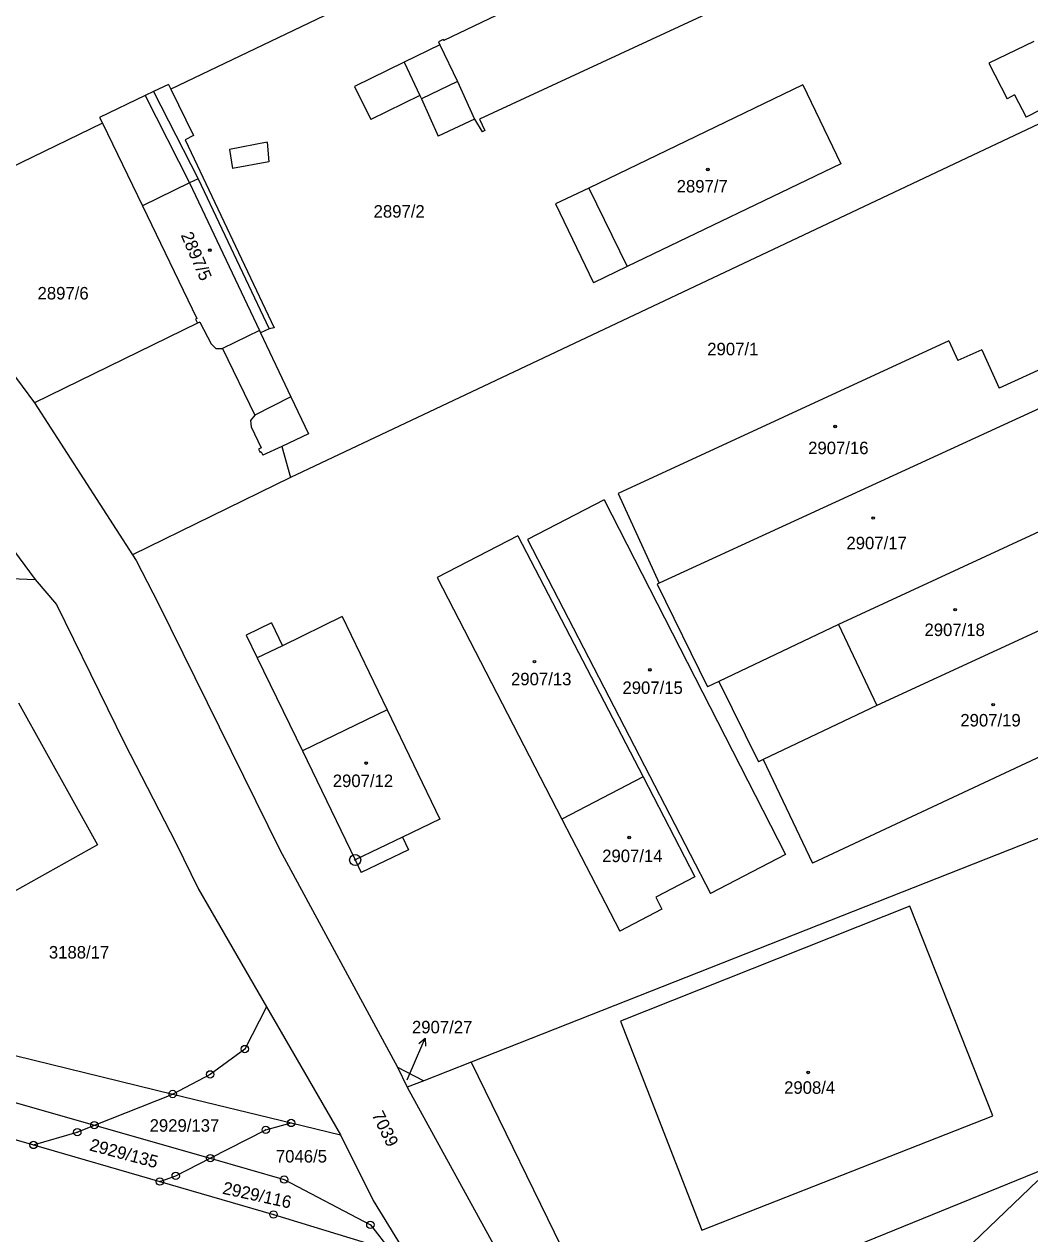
# Model space of a CAD drawing. Extents: x -593183 to -588034, y -1130415 to -1124994.
# Drawn here: x -591710.2 to -591573.4, y -1128134.3 to -1127969.7 of the extents above; entities that cross this region are included whole.
import ezdxf

# ---------------------------------------------------------------- set-up
doc = ezdxf.new("R2010")
doc.units = 0
for name, color, linetype in [('Vrstva 1', 7, 'Continuous'), ('Vrstva 16', 7, 'Continuous'), ('Vrstva 18', 7, 'Continuous'), ('Vrstva 19', 7, 'Continuous'), ('Vrstva 24', 7, 'Continuous'), ('Vrstva 25', 7, 'Continuous'), ('Vrstva 4', 7, 'Continuous')]:
    doc.layers.add(name, color=color, linetype=linetype)

msp = doc.modelspace()

# ---------------------------------------------------------------- linework, layer by layer
at = {"layer": 'Vrstva 1'}
for p, q in [((-591579.21, -1127925.41), (-591690.25, -1127978.58)), ((-591617.79, -1127955.04), (-591653.11, -1127971.96)), ((-591611.84, -1127965.78), (-591648.23, -1127982.66)), ((-591653.17, -1127971.83), (-591653.83, -1127972.14)), ((-591653.17, -1127971.83), (-591653.11, -1127971.96)), ((-591653.63, -1127972.55), (-591658.5, -1127974.93)), ((-591653.83, -1127972.14), (-591653.63, -1127972.55)), ((-591572.8, -1127972.09), (-591578.95, -1127975.03)), ((-591553.24, -1127974.41), (-591673.98, -1128031.42)), ((-591658.5, -1127974.93), (-591665.23, -1127978.21)), ((-591578.95, -1127975.03), (-591576.44, -1127979.88)), ((-591690.56, -1127977.93), (-591692.62, -1127978.92)), ((-591690.56, -1127977.93), (-591690.25, -1127978.58)), ((-591665.23, -1127978.21), (-591663.02, -1127982.72)), ((-591604.23, -1127977.99), (-591633.37, -1127992.03)), ((-591604.23, -1127977.99), (-591599.06, -1127988.76)), ((-591693.72, -1127979.45), (-591699.93, -1127982.45)), ((-591692.62, -1127978.92), (-591693.72, -1127979.45)), ((-591690.25, -1127978.58), (-591687.18, -1127984.91)), ((-591656.34, -1127979.46), (-591663.02, -1127982.72)), ((-591656.34, -1127979.46), (-591656.12, -1127979.91)), ((-591656.12, -1127979.91), (-591653.88, -1127985)), ((-591575.43, -1127979.36), (-591576.44, -1127979.88)), ((-591575.43, -1127979.36), (-591573.85, -1127982.4)), ((-591569.04, -1127979.92), (-591573.85, -1127982.4)), ((-591699.56, -1127983.22), (-591725.5, -1127995.8)), ((-591699.93, -1127982.45), (-591699.56, -1127983.22)), ((-591699.56, -1127983.22), (-591694.12, -1127994.46)), ((-591648.94, -1127982.66), (-591653.88, -1127985)), ((-591648.94, -1127982.66), (-591647.9, -1127984.39)), ((-591648.23, -1127982.66), (-591647.51, -1127984.21)), ((-591687.18, -1127984.91), (-591688.3, -1127985.46)), ((-591647.51, -1127984.21), (-591647.9, -1127984.39)), ((-591688.3, -1127985.46), (-591676.17, -1128011.05)), ((-591599.06, -1127988.76), (-591628.14, -1128002.7)), ((-591633.37, -1127992.03), (-591637.88, -1127994.2)), ((-591694.12, -1127994.46), (-591686.71, -1128009.79)), ((-591637.88, -1127994.2), (-591632.74, -1128004.91)), ((-591628.14, -1128002.7), (-591632.74, -1128004.91)), ((-591717.83, -1128009.1), (-591708.79, -1128021.27)), ((-591686.61, -1128010.41), (-591708.79, -1128021.27)), ((-591686.71, -1128009.79), (-591686.87, -1128009.87)), ((-591686.87, -1128009.87), (-591686.61, -1128010.41)), ((-591686.31, -1128010.27), (-591686.61, -1128010.41)), ((-591686.31, -1128010.27), (-591684.76, -1128013.22)), ((-591676.86, -1128011.19), (-591678.02, -1128011.74)), ((-591676.17, -1128011.05), (-591676.86, -1128011.19)), ((-591678.02, -1128011.74), (-591673.91, -1128020.42)), ((-591584.38, -1128012.82), (-591629.39, -1128033.58)), ((-591584.38, -1128012.82), (-591583.14, -1128015.51)), ((-591684.76, -1128013.22), (-591684.1, -1128013.85)), ((-591684.1, -1128013.85), (-591683.22, -1128013.86)), ((-591683.22, -1128013.86), (-591678.8, -1128022.93)), ((-591579.9, -1128014.03), (-591583.14, -1128015.51)), ((-591579.9, -1128014.03), (-591577.51, -1128019.24)), ((-591567.77, -1128014.77), (-591577.51, -1128019.24)), ((-591566.36, -1128019.38), (-591623.78, -1128045.8)), ((-591708.79, -1128021.27), (-591695.48, -1128041.92)), ((-591673.91, -1128020.42), (-591671.51, -1128025.47)), ((-591678.8, -1128022.93), (-591679.41, -1128023.63)), ((-591679.41, -1128023.63), (-591679.32, -1128024.5)), ((-591679.32, -1128024.5), (-591677.96, -1128027.37)), ((-591671.51, -1128025.47), (-591675.16, -1128027.19)), ((-591677.96, -1128027.37), (-591678.3, -1128027.54)), ((-591678.3, -1128027.54), (-591678.11, -1128028)), ((-591675.16, -1128027.19), (-591677.72, -1128028.39)), ((-591677.95, -1128027.92), (-591678.11, -1128028)), ((-591677.95, -1128027.92), (-591677.72, -1128028.39)), ((-591673.98, -1128031.42), (-591695.48, -1128041.92)), ((-591717.29, -1128033.73), (-591708.7, -1128045.26)), ((-591631.29, -1128034.44), (-591641.72, -1128039.83)), ((-591631.29, -1128034.44), (-591606.61, -1128082.7)), ((-591629.39, -1128033.58), (-591623.78, -1128045.8)), ((-591559.94, -1128033.16), (-591599.4, -1128051.4)), ((-591643.01, -1128039.33), (-591654.01, -1128044.99)), ((-591643.01, -1128039.33), (-591625.98, -1128072.13)), ((-591641.72, -1128039.83), (-591616.82, -1128088.01)), ((-591695.48, -1128041.92), (-591694.95, -1128042.68)), ((-591694.95, -1128042.68), (-591691.94, -1128048.6)), ((-591554.77, -1128044.23), (-591594.16, -1128062.43)), ((-591711.95, -1128045.16), (-591708.7, -1128045.26)), ((-591708.7, -1128045.26), (-591705.79, -1128048.66)), ((-591654.01, -1128044.99), (-591637.02, -1128077.86)), ((-591623.78, -1128045.8), (-591624.05, -1128045.93)), ((-591624.05, -1128045.93), (-591617.21, -1128059.87)), ((-591705.79, -1128048.66), (-591696.54, -1128067.54)), ((-591691.94, -1128048.6), (-591675.39, -1128082.06)), ((-591666.91, -1128050.32), (-591675.04, -1128054.28)), ((-591666.91, -1128050.32), (-591660.8, -1128063.02)), ((-591676.56, -1128051.16), (-591679.99, -1128052.83)), ((-591676.56, -1128051.16), (-591675.04, -1128054.28)), ((-591599.4, -1128051.4), (-591615.68, -1128059.14)), ((-591679.99, -1128052.83), (-591678.48, -1128055.95)), ((-591678.48, -1128055.95), (-591672.34, -1128068.57)), ((-591548.21, -1128058.27), (-591602.93, -1128083.84)), ((-591615.68, -1128059.14), (-591617.21, -1128059.87)), ((-591615.68, -1128059.14), (-591610.28, -1128070.1)), ((-591710.97, -1128062.06), (-591700.21, -1128081.39)), ((-591660.8, -1128063.02), (-591653.64, -1128077.88)), ((-591594.16, -1128062.43), (-591609.62, -1128069.78)), ((-591696.54, -1128067.54), (-591689.55, -1128081.1)), ((-591672.34, -1128068.57), (-591665.16, -1128083.43)), ((-591609.62, -1128069.78), (-591610.28, -1128070.1)), ((-591609.62, -1128069.78), (-591602.93, -1128083.84)), ((-591625.98, -1128072.13), (-591637.02, -1128077.86)), ((-591625.98, -1128072.13), (-591618.93, -1128085.71)), ((-591653.64, -1128077.88), (-591658.72, -1128080.33)), ((-591565.82, -1128078), (-591649.36, -1128110.92)), ((-591637.02, -1128077.86), (-591629.13, -1128093.09)), ((-591658.72, -1128080.33), (-591657.9, -1128082.04)), ((-591700.21, -1128081.39), (-591732.34, -1128099.27)), ((-591689.55, -1128081.1), (-591686.48, -1128087.39)), ((-591675.39, -1128082.06), (-591659.42, -1128111.62)), ((-591657.9, -1128082.04), (-591664.34, -1128085.14)), ((-591665.16, -1128083.43), (-591664.34, -1128085.14)), ((-591606.61, -1128082.7), (-591616.82, -1128088.01)), ((-591618.93, -1128085.71), (-591624.26, -1128088.48)), ((-591686.48, -1128087.39), (-591677.24, -1128103.39)), ((-591624.26, -1128088.48), (-591623.41, -1128090.12)), ((-591623.41, -1128090.12), (-591629.13, -1128093.09)), ((-591589.66, -1128089.73), (-591629.05, -1128105.35)), ((-591578.4, -1128118.21), (-591589.66, -1128089.73)), ((-591677.24, -1128103.39), (-591672.06, -1128112.34)), ((-591629.05, -1128105.35), (-591617.98, -1128133.79)), ((-591714.22, -1128109.35), (-591689.99, -1128115.26)), ((-591659.42, -1128111.62), (-591655.81, -1128113.45)), ((-591659.42, -1128111.62), (-591658.08, -1128114.33)), ((-591649.36, -1128110.92), (-591655.81, -1128113.45)), ((-591672.06, -1128112.34), (-591667.17, -1128120.83)), ((-591720.46, -1128113.87), (-591700.65, -1128119.51)), ((-591655.81, -1128113.45), (-591658.08, -1128114.33)), ((-591658.08, -1128114.33), (-591642.48, -1128142.73)), ((-591700.65, -1128119.51), (-591689.99, -1128115.26)), ((-591689.99, -1128115.26), (-591673.87, -1128119.2)), ((-591617.98, -1128133.79), (-591578.4, -1128118.21)), ((-591721.84, -1128118.45), (-591708.93, -1128122.19)), ((-591702.97, -1128120.46), (-591700.65, -1128119.51)), ((-591700.65, -1128119.51), (-591684.87, -1128124)), ((-591677.33, -1128120.13), (-591673.87, -1128119.2)), ((-591673.87, -1128119.2), (-591667.17, -1128120.83)), ((-591708.93, -1128122.19), (-591702.97, -1128120.46)), ((-591684.87, -1128124), (-591677.33, -1128120.13)), ((-591667.17, -1128120.83), (-591662.73, -1128129.74)), ((-591708.93, -1128122.19), (-591691.74, -1128127.17)), ((-591689.58, -1128126.4), (-591684.87, -1128124)), ((-591684.87, -1128124), (-591674.81, -1128126.9)), ((-591570.02, -1128124.92), (-591630.51, -1128149.5)), ((-591691.74, -1128127.17), (-591689.58, -1128126.4)), ((-591691.74, -1128127.17), (-591676.28, -1128131.65)), ((-591674.81, -1128126.9), (-591663.09, -1128133.05)), ((-591572.28, -1128127.04), (-591581.11, -1128135.51)), ((-591662.73, -1128129.74), (-591651.34, -1128148.21)), ((-591676.28, -1128131.65), (-591660.4, -1128136.52)), ((-591663.09, -1128133.05), (-591660.4, -1128136.52))]:
    msp.add_line(p, q, dxfattribs=at)
at = {"layer": 'Vrstva 16'}
msp.add_line((-591658.1, -1128113.35), (-591656.82, -1128110.4), dxfattribs=at)
at = {"layer": 'Vrstva 24'}
for centre, radius in [((-591665.16, -1128083.43), 0.75), ((-591665.16, -1128083.43), 0.0903), ((-591680.17, -1128109.14), 0.5), ((-591680.17, -1128109.14), 0.0327), ((-591684.9, -1128112.59), 0.5), ((-591684.9, -1128112.59), 0.0327), ((-591689.99, -1128115.26), 0.5), ((-591689.99, -1128115.26), 0.0327), ((-591702.97, -1128120.46), 0.5), ((-591700.65, -1128119.51), 0.5), ((-591700.65, -1128119.51), 0.0327), ((-591677.33, -1128120.13), 0.5), ((-591673.87, -1128119.2), 0.5), ((-591673.87, -1128119.2), 0.0327), ((-591702.97, -1128120.46), 0.0327), ((-591677.33, -1128120.13), 0.0327), ((-591708.93, -1128122.19), 0.5), ((-591708.93, -1128122.19), 0.0327), ((-591684.87, -1128124), 0.5), ((-591684.87, -1128124), 0.0327), ((-591689.58, -1128126.4), 0.5), ((-591689.58, -1128126.4), 0.0327), ((-591674.81, -1128126.9), 0.5), ((-591691.74, -1128127.17), 0.5), ((-591691.74, -1128127.17), 0.0327), ((-591674.81, -1128126.9), 0.0327), ((-591676.28, -1128131.65), 0.5), ((-591676.28, -1128131.65), 0.0327), ((-591663.09, -1128133.05), 0.5), ((-591663.09, -1128133.05), 0.0327)]:
    msp.add_circle(centre, radius, dxfattribs=at)
at = {"layer": 'Vrstva 25'}
msp.add_line((-591656.82, -1128110.4), (-591655.63, -1128107.65), dxfattribs=at)
msp.add_lwpolyline([(-591656.48, -1128108.37), (-591655.63, -1128107.65), (-591655.57, -1128108.76)], dxfattribs=at)
for centre, radius in [((-591617.16, -1127989.52), 0.175), ((-591617.16, -1127989.52), 0.15), ((-591684.94, -1128000.49), 0.175), ((-591684.94, -1128000.49), 0.15), ((-591599.85, -1128024.47), 0.175), ((-591599.85, -1128024.47), 0.15), ((-591594.67, -1128036.92), 0.175), ((-591594.67, -1128036.92), 0.15), ((-591583.51, -1128049.38), 0.175), ((-591583.51, -1128049.38), 0.15), ((-591640.77, -1128056.46), 0.175), ((-591640.77, -1128056.46), 0.15), ((-591625.05, -1128057.57), 0.175), ((-591625.05, -1128057.57), 0.15), ((-591578.34, -1128062.31), 0.175), ((-591578.34, -1128062.31), 0.15), ((-591663.67, -1128070.25), 0.175), ((-591663.67, -1128070.25), 0.15), ((-591627.86, -1128080.37), 0.175), ((-591627.86, -1128080.37), 0.15), ((-591603.51, -1128112.32), 0.175), ((-591603.51, -1128112.32), 0.15)]:
    msp.add_circle(centre, radius, dxfattribs=at)
at = {"layer": 'Vrstva 4'}
for p, q in [((-591653.63, -1127972.55), (-591651.25, -1127977.53)), ((-591658.5, -1127974.93), (-591656.34, -1127979.46)), ((-591651.25, -1127977.53), (-591656.12, -1127979.91)), ((-591651.25, -1127977.53), (-591648.94, -1127982.66)), ((-591693.72, -1127979.45), (-591687.71, -1127991.32)), ((-591692.62, -1127978.92), (-591686.54, -1127990.77)), ((-591677.15, -1127985.78), (-591682.28, -1127986.81)), ((-591677.15, -1127985.78), (-591676.91, -1127988.45)), ((-591682.28, -1127986.81), (-591681.83, -1127989.38)), ((-591676.91, -1127988.45), (-591681.83, -1127989.38)), ((-591687.71, -1127991.32), (-591694.12, -1127994.46)), ((-591686.54, -1127990.77), (-591687.71, -1127991.32)), ((-591687.71, -1127991.32), (-591678.18, -1128011.42)), ((-591686.54, -1127990.77), (-591676.86, -1128011.19)), ((-591633.37, -1127992.03), (-591628.14, -1128002.7)), ((-591678.18, -1128011.42), (-591683.22, -1128013.86)), ((-591678.18, -1128011.42), (-591678.02, -1128011.74)), ((-591673.91, -1128020.42), (-591678.8, -1128022.93)), ((-591675.16, -1128027.19), (-591673.98, -1128031.42)), ((-591599.4, -1128051.4), (-591594.16, -1128062.43)), ((-591675.04, -1128054.28), (-591678.48, -1128055.95)), ((-591660.8, -1128063.02), (-591672.34, -1128068.57)), ((-591658.72, -1128080.33), (-591665.16, -1128083.43)), ((-591677.24, -1128103.39), (-591680.17, -1128109.14)), ((-591680.17, -1128109.14), (-591684.9, -1128112.59)), ((-591649.36, -1128110.92), (-591630.51, -1128149.5)), ((-591684.9, -1128112.59), (-591689.99, -1128115.26))]:
    msp.add_line(p, q, dxfattribs=at)

# ---------------------------------------------------------------- texts
at = {"layer": 'Vrstva 16'}
msp.add_text('2907/27', height=1.7, dxfattribs=at).set_placement((-591657.43, -1128107.01))
at = {"layer": 'Vrstva 18'}
for s, height, p in [('2897/2', 1.7, (-591662.65, -1127996.06)), ('2897/6', 1.7, (-591708.38, -1128007.19)), ('2907/1', 1.7, (-591617.25, -1128014.78)), ('3188/17', 1.7, (-591706.84, -1128096.83)), ('2907/27', 0.1, (-591658.1, -1128113.35)), ('2929/137', 1.7, (-591693.13, -1128120.39)), ('7046/5', 1.7, (-591675.95, -1128124.58))]:
    msp.add_text(s, height=height, dxfattribs=at).set_placement(p)
for s, rotation, p in [('7039', 296.3011, (-591662.95, -1128118.09)), ('2929/135', 345.0506, (-591701.42, -1128122.92)), ('2929/116', 347.5768, (-591683.31, -1128128.81))]:
    msp.add_text(s, height=1.7, rotation=rotation, dxfattribs=at).set_placement(p)
at = {"layer": 'Vrstva 19'}
for s, p in [('2897/7', (-591621.41, -1127992.64)), ('2907/16', (-591603.52, -1128028.23)), ('2907/17', (-591598.31, -1128041.17)), ('2907/18', (-591587.69, -1128052.97)), ('2907/13', (-591643.95, -1128059.67)), ('2907/15', (-591628.79, -1128060.85)), ('2907/19', (-591582.81, -1128065.27)), ('2907/12', (-591668.21, -1128073.51)), ('2907/14', (-591631.55, -1128083.72)), ('2908/4', (-591606.79, -1128115.23))]:
    msp.add_text(s, height=1.7, dxfattribs=at).set_placement(p)
msp.add_text('2897/5', height=1.7, rotation=293.3555, dxfattribs=at).set_placement((-591688.92, -1127998.43))

doc.saveas('drawing.dxf')
